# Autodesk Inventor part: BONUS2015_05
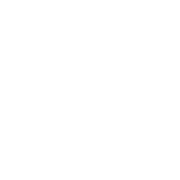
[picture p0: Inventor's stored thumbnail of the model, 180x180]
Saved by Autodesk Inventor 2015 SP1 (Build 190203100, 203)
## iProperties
Created: 2015-05
Part Number: BONUS2015_05
Material: Generisch
Document SubType Name: Modeling
Density: 1 g/cm^3
Appearance: Vorgabe
xx: 05
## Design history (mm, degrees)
